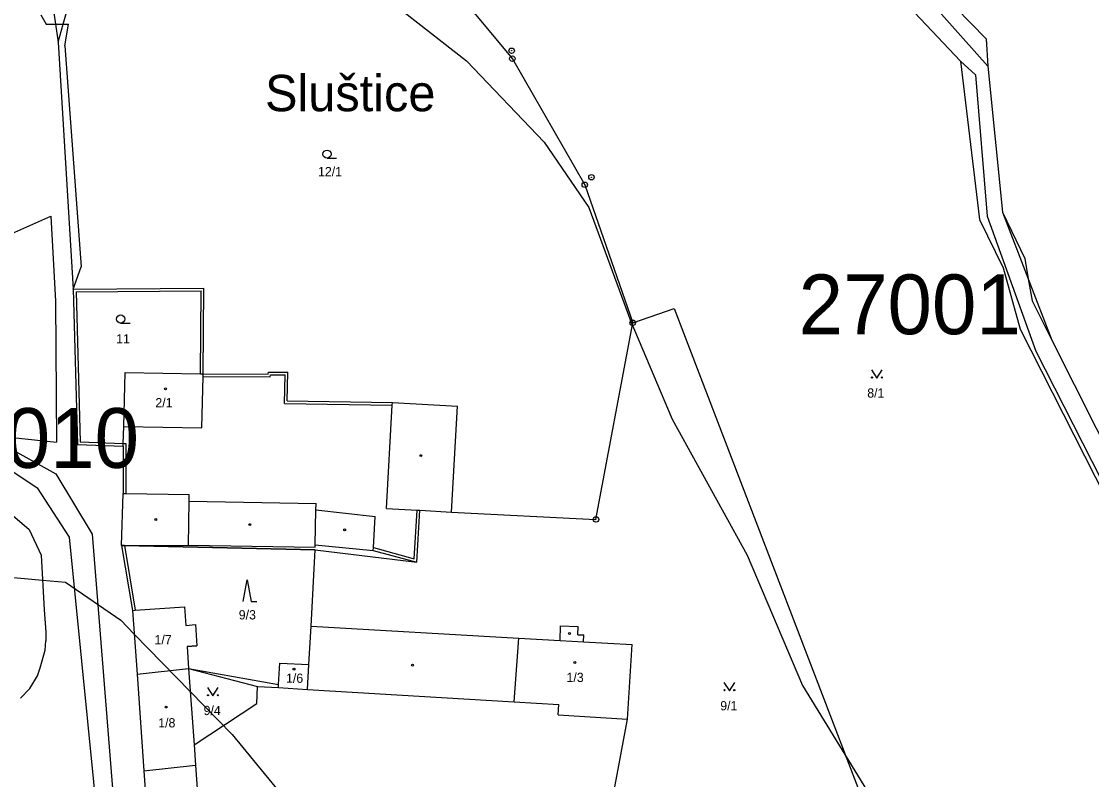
# Model space of a CAD drawing. Extents: x -725765 to -723182, y -1052705 to -1049154.
# Drawn here: x -724689.6 to -724492.6, y -1050911.3 to -1050771.8 of the extents above; entities that cross this region are included whole.
import ezdxf

# ---------------------------------------------------------------- set-up
doc = ezdxf.new("R2010")
doc.units = 0
for name, color, linetype in [('Vrstva 1', 7, 'Continuous'), ('Vrstva 15', 7, 'Continuous'), ('Vrstva 18', 7, 'Continuous'), ('Vrstva 19', 7, 'Continuous'), ('Vrstva 25', 7, 'Continuous'), ('Vrstva 4', 7, 'Continuous'), ('Vrstva 52', 7, 'Continuous'), ('Vrstva 53', 7, 'Continuous')]:
    doc.layers.add(name, color=color, linetype=linetype)

msp = doc.modelspace()

# ---------------------------------------------------------------- linework, layer by layer
at = {"layer": 'Vrstva 1'}
for points in [[(-724681.91, -1050772.28), (-724672.23, -1050738.03)], [(-724538.38, -1050749.99), (-724511.63, -1050779.98)], [(-724686.37, -1050751.98), (-724683.34, -1050772.29)], [(-724540.92, -1050753.35), (-724516.71, -1050779.1)], [(-724616.48, -1050757.85), (-724599.21, -1050778.62)], [(-724683.34, -1050772.29), (-724682.85, -1050775.6)], [(-724682.85, -1050775.6), (-724681.91, -1050772.28)], [(-724682.85, -1050775.6), (-724680.06, -1050821.02)], [(-724599.21, -1050778.62), (-724585.88, -1050801.83)], [(-724516.71, -1050779.1), (-724513.92, -1050781.58)], [(-724511.63, -1050779.98), (-724508.94, -1050806.85)], [(-724513.92, -1050781.58), (-724511.8, -1050807.6)], [(-724585.88, -1050801.83), (-724577.05, -1050827.24)], [(-724691.91, -1050811.03), (-724684.21, -1050807.61)], [(-724684.21, -1050807.61), (-724683.32, -1050823.25)], [(-724511.8, -1050807.6), (-724502.81, -1050832.47)], [(-724508.94, -1050806.85), (-724504.2, -1050819.15)], [(-724504.2, -1050819.15), (-724499.87, -1050830.41)], [(-724680.06, -1050821.02), (-724656.03, -1050820.88)], [(-724680.06, -1050821.02), (-724679.28, -1050849.63)], [(-724656.14, -1050836.64), (-724656.03, -1050820.88)], [(-724683.32, -1050823.25), (-724683.14, -1050849.22)], [(-724577.05, -1050827.24), (-724569.4, -1050824.59)], [(-724569.4, -1050824.59), (-724528.23, -1050932)], [(-724583.81, -1050863.44), (-724577.05, -1050827.24)], [(-724499.87, -1050830.41), (-724479.42, -1050870.99)], [(-724502.81, -1050832.47), (-724482.2, -1050872.94)], [(-724670.74, -1050846.33), (-724670.52, -1050836.4)], [(-724670.52, -1050836.4), (-724656.64, -1050836.63)], [(-724656.64, -1050836.63), (-724656.14, -1050836.64)], [(-724656.14, -1050836.64), (-724644.2, -1050836.67)], [(-724644.2, -1050836.67), (-724644.14, -1050836.32)], [(-724644.14, -1050836.32), (-724640.54, -1050836.33)], [(-724640.68, -1050841.61), (-724640.54, -1050836.33)], [(-724640.68, -1050841.61), (-724621.3, -1050841.91)], [(-724621.3, -1050841.91), (-724609.3, -1050842.57)], [(-724610.42, -1050862.09), (-724609.3, -1050842.57)], [(-724670.87, -1050849.43), (-724670.74, -1050846.33)], [(-724699.44, -1050847.52), (-724683.14, -1050849.22)], [(-724679.28, -1050849.63), (-724670.89, -1050849.93)], [(-724670.89, -1050849.93), (-724670.87, -1050849.43)], [(-724670.89, -1050849.93), (-724670.86, -1050858.65)], [(-724671.16, -1050868.22), (-724670.86, -1050858.65)], [(-724694.75, -1050859.69), (-724688.19, -1050865.28)], [(-724616.81, -1050871.32), (-724616.26, -1050861.75)], [(-724616.26, -1050861.75), (-724610.42, -1050862.09)], [(-724610.42, -1050862.09), (-724583.81, -1050863.44)], [(-724688.19, -1050865.28), (-724685.99, -1050869.99)], [(-724671.16, -1050868.22), (-724670.65, -1050868.23)], [(-724671.16, -1050868.22), (-724669.15, -1050880.2)], [(-724670.65, -1050868.23), (-724635.54, -1050869.06)], [(-724685.99, -1050869.99), (-724685.42, -1050880.08)], [(-724636.24, -1050883.08), (-724635.54, -1050869.06)], [(-724635.54, -1050869.06), (-724616.81, -1050871.32)], [(-724685.42, -1050880.08), (-724685.14, -1050884.21)], [(-724669.15, -1050880.2), (-724668.64, -1050880.16)], [(-724669.15, -1050880.2), (-724668.32, -1050891.93)], [(-724668.64, -1050880.16), (-724659.59, -1050879.54)], [(-724659.59, -1050879.54), (-724659.36, -1050882.97)], [(-724685.14, -1050884.21), (-724685.13, -1050885.78)], [(-724659.36, -1050882.97), (-724657.53, -1050882.8)], [(-724657.53, -1050882.8), (-724657.3, -1050886.68)], [(-724636.68, -1050890.14), (-724636.24, -1050883.08)], [(-724636.24, -1050883.08), (-724598, -1050885.27)], [(-724685.27, -1050887.49), (-724685.13, -1050885.78)], [(-724598.9, -1050896.99), (-724598, -1050885.27)], [(-724598, -1050885.27), (-724590.41, -1050885.7)], [(-724590.41, -1050885.7), (-724586.11, -1050885.95)], [(-724586.11, -1050885.95), (-724577.17, -1050886.46)], [(-724578.03, -1050900.23), (-724577.17, -1050886.46)], [(-724686.14, -1050890.78), (-724685.27, -1050887.49)], [(-724659.11, -1050886.82), (-724657.3, -1050886.68)], [(-724659.11, -1050886.82), (-724658.84, -1050890.87)], [(-724642.26, -1050893.8), (-724642.04, -1050889.9)], [(-724642.04, -1050889.9), (-724636.68, -1050890.14)], [(-724636.96, -1050894.71), (-724636.68, -1050890.14)], [(-724688.06, -1050894.53), (-724686.65, -1050892.25)], [(-724686.65, -1050892.25), (-724686.14, -1050890.78)], [(-724668.32, -1050891.93), (-724658.84, -1050890.87)], [(-724668.32, -1050891.93), (-724667.07, -1050909.73)], [(-724658.84, -1050890.87), (-724657.83, -1050904.95)], [(-724658.84, -1050890.87), (-724646.15, -1050894.16)], [(-724646.28, -1050897.31), (-724646.15, -1050894.16)], [(-724646.15, -1050894.16), (-724642.29, -1050894.39)], [(-724642.29, -1050894.39), (-724642.26, -1050893.8)], [(-724642.29, -1050894.39), (-724636.96, -1050894.71)], [(-724689.77, -1050896.34), (-724688.06, -1050894.53)], [(-724657.83, -1050904.95), (-724646.28, -1050897.31)], [(-724598.9, -1050896.99), (-724590.63, -1050897.48)], [(-724590.75, -1050899.43), (-724590.63, -1050897.48)], [(-724590.75, -1050899.43), (-724578.03, -1050900.23)], [(-724580.49, -1050913.34), (-724578.03, -1050900.23)], [(-724657.83, -1050904.95), (-724657.57, -1050908.64)], [(-724667.07, -1050909.73), (-724657.57, -1050908.64)], [(-724667.07, -1050909.73), (-724662.84, -1050969.87)]]:
    msp.add_lwpolyline(points, dxfattribs=at)
at = {"layer": 'Vrstva 25'}
for points in [[(-724633.34, -1050796.93), (-724631.59, -1050796.93)], [(-724671.35, -1050827.29), (-724669.6, -1050827.29)], [(-724533.09, -1050835.9), (-724532.09, -1050837.4), (-724531.09, -1050835.9)], [(-724648.79, -1050878.53), (-724648.04, -1050874.53), (-724647.29, -1050878.53), (-724646.29, -1050878.53)], [(-724655.36, -1050894.4), (-724654.36, -1050895.9), (-724653.36, -1050894.4)], [(-724560.24, -1050893.46), (-724559.24, -1050894.96), (-724558.24, -1050893.46)]]:
    msp.add_lwpolyline(points, dxfattribs=at)
for centre, radius in [((-724599.34, -1050777.15), 0.5), ((-724599.21, -1050778.62), 0.5), ((-724599.34, -1050777.15), 0.032), ((-724599.21, -1050778.62), 0.032), ((-724633.34, -1050796.18), 0.75), ((-724585.88, -1050801.83), 0.5), ((-724585.88, -1050801.83), 0.032), ((-724584.65, -1050800.44), 0.5), ((-724584.65, -1050800.44), 0.032), ((-724671.35, -1050826.54), 0.75), ((-724577.05, -1050827.24), 0.5), ((-724577.05, -1050827.24), 0.032), ((-724532.99, -1050837.3), 0.1), ((-724531.19, -1050837.3), 0.1), ((-724663.09, -1050839.41), 0.175), ((-724616.04, -1050851.69), 0.175), ((-724664.89, -1050863.43), 0.175), ((-724647.57, -1050864.39), 0.175), ((-724583.81, -1050863.44), 0.5), ((-724583.81, -1050863.44), 0.032), ((-724630.09, -1050865.35), 0.175), ((-724588.7, -1050884.44), 0.175), ((-724617.59, -1050890.27), 0.175), ((-724587.7, -1050889.78), 0.175), ((-724639.42, -1050890.99), 0.175), ((-724655.26, -1050895.8), 0.1), ((-724653.46, -1050895.8), 0.1), ((-724560.14, -1050894.86), 0.1), ((-724558.34, -1050894.86), 0.1), ((-724662.96, -1050897.97), 0.175)]:
    msp.add_circle(centre, radius, dxfattribs=at)
at = {"layer": 'Vrstva 4'}
for points in [[(-724537.52, -1050748.85), (-724511.99, -1050774.95)], [(-724686.05, -1050770.54), (-724685.05, -1050772.29)], [(-724685.05, -1050772.29), (-724683.34, -1050772.29)], [(-724683.34, -1050772.29), (-724681.91, -1050772.28)], [(-724681.91, -1050772.28), (-724680.94, -1050772.28)], [(-724681.59, -1050776.24), (-724680.94, -1050772.28)], [(-724511.99, -1050774.95), (-724511.63, -1050779.98)], [(-724681.59, -1050776.24), (-724678.6, -1050816.92)], [(-724516.71, -1050779.1), (-724513.17, -1050808.2)], [(-724508.94, -1050806.85), (-724504.85, -1050815.38)], [(-724513.17, -1050808.2), (-724508.86, -1050817.12)], [(-724504.85, -1050815.38), (-724504.2, -1050819.15)], [(-724680.06, -1050821.02), (-724678.6, -1050816.92)], [(-724508.86, -1050817.12), (-724505.7, -1050828.43)], [(-724504.2, -1050819.15), (-724503.51, -1050823.2)], [(-724679.55, -1050821.52), (-724656.53, -1050821.38)], [(-724679.55, -1050821.52), (-724678.79, -1050849.15)], [(-724656.64, -1050836.63), (-724656.53, -1050821.38)], [(-724503.51, -1050823.2), (-724499.87, -1050830.41)], [(-724505.7, -1050828.43), (-724482.04, -1050875.06)], [(-724656.37, -1050846.6), (-724656.15, -1050837.14)], [(-724656.15, -1050837.14), (-724656.14, -1050836.64)], [(-724656.15, -1050837.14), (-724643.78, -1050837.17)], [(-724643.78, -1050837.17), (-724643.72, -1050836.82)], [(-724643.72, -1050836.82), (-724641.05, -1050836.83)], [(-724641.19, -1050842.1), (-724641.05, -1050836.83)], [(-724641.19, -1050842.1), (-724621.33, -1050842.41)], [(-724622.41, -1050861.39), (-724621.33, -1050842.41)], [(-724621.33, -1050842.41), (-724621.3, -1050841.91)], [(-724670.74, -1050846.33), (-724656.37, -1050846.6)], [(-724691.02, -1050850.72), (-724683.3, -1050855.06)], [(-724678.79, -1050849.15), (-724670.87, -1050849.43)], [(-724670.87, -1050849.43), (-724670.39, -1050849.45)], [(-724670.39, -1050849.45), (-724670.36, -1050858.66)], [(-724691.95, -1050854.12), (-724686.7, -1050857.6)], [(-724683.3, -1050855.06), (-724676.58, -1050866.15)], [(-724686.7, -1050857.6), (-724680.8, -1050866.72)], [(-724670.86, -1050858.65), (-724670.36, -1050858.66)], [(-724670.36, -1050858.66), (-724658.71, -1050858.85)], [(-724658.73, -1050860.1), (-724658.71, -1050858.85)], [(-724658.86, -1050868.16), (-724658.73, -1050860.1)], [(-724658.73, -1050860.1), (-724635.36, -1050860.52)], [(-724635.38, -1050861.66), (-724635.36, -1050860.52)], [(-724635.5, -1050868.13), (-724635.38, -1050861.66)], [(-724635.38, -1050861.66), (-724624.46, -1050862.88)], [(-724624.79, -1050868.63), (-724624.46, -1050862.88)], [(-724622.41, -1050861.39), (-724616.76, -1050861.72)], [(-724617.27, -1050870.68), (-724616.76, -1050861.72)], [(-724616.76, -1050861.72), (-724616.26, -1050861.75)], [(-724680.8, -1050866.72), (-724674.09, -1050934.57)], [(-724676.58, -1050866.15), (-724671.12, -1050934.45)], [(-724671.16, -1050868.22), (-724658.86, -1050868.16)], [(-724670.65, -1050868.23), (-724668.64, -1050880.16)], [(-724658.86, -1050868.16), (-724635.51, -1050868.53)], [(-724635.51, -1050868.53), (-724635.5, -1050868.13)], [(-724635.5, -1050868.13), (-724624.82, -1050869.14)], [(-724624.82, -1050869.14), (-724624.79, -1050868.63)], [(-724624.79, -1050868.63), (-724617.27, -1050870.68)], [(-724624.82, -1050869.14), (-724616.81, -1050871.32)], [(-724590.41, -1050885.7), (-724590.33, -1050883)], [(-724590.33, -1050883), (-724587.12, -1050883.17)], [(-724587.14, -1050884.67), (-724587.12, -1050883.17)], [(-724587.14, -1050884.67), (-724586.06, -1050884.67)], [(-724586.11, -1050885.95), (-724586.06, -1050884.67)], [(-724658.84, -1050890.87), (-724642.26, -1050893.8)], [(-724636.96, -1050894.71), (-724598.9, -1050896.99)], [(-724657.57, -1050908.64), (-724654.32, -1050954.36)]]:
    msp.add_lwpolyline(points, dxfattribs=at)
at = {"layer": 'Vrstva 52'}
for points in [[(-724581.64, -1050708.13), (-724564.23, -1050728.57), (-724563.61, -1050729.23), (-724540.92, -1050753.35), (-724516.71, -1050779.1), (-724513.92, -1050781.58), (-724511.8, -1050807.6), (-724502.81, -1050832.47), (-724482.2, -1050872.94), (-724474.53, -1050880.96), (-724469.4, -1050885.71), (-724460.7, -1050890.93), (-724440.66, -1050902.59), (-724425.28, -1050906.29), (-724411.67, -1050908.97), (-724400.33, -1050906.21), (-724381.77, -1050899.99)], [(-724733.3, -1050722.26), (-724731.38, -1050724), (-724718.63, -1050730), (-724709.97, -1050732.26), (-724695.63, -1050736), (-724671.88, -1050741), (-724646.63, -1050753), (-724630.63, -1050761), (-724607.63, -1050779), (-724593.38, -1050794), (-724585.13, -1050806), (-724577.38, -1050827), (-724569.81, -1050845), (-724556, -1050870), (-724545.81, -1050894), (-724531.69, -1050917), (-724517.63, -1050935), (-724505.66, -1050947.46)], [(-724669.15, -1050880.2), (-724668.64, -1050880.16), (-724659.59, -1050879.54), (-724659.36, -1050882.97), (-724657.53, -1050882.8), (-724657.3, -1050886.68), (-724659.11, -1050886.82), (-724658.84, -1050890.87), (-724646.15, -1050894.16), (-724642.29, -1050894.39), (-724642.26, -1050893.8), (-724642.04, -1050889.9), (-724636.68, -1050890.14), (-724636.24, -1050883.08), (-724635.54, -1050869.06), (-724670.65, -1050868.23), (-724671.16, -1050868.22), (-724669.15, -1050880.2)], [(-724724.93, -1050961.09), (-724723.69, -1050959), (-724719.26, -1050944.99), (-724718.63, -1050943), (-724717.88, -1050938.42), (-724717.26, -1050934.62), (-724715.44, -1050923.42), (-724715.38, -1050923), (-724712.88, -1050902.63), (-724712.19, -1050897), (-724707.69, -1050884), (-724700.69, -1050877), (-724692.38, -1050874), (-724685.73, -1050874.61), (-724681.5, -1050875), (-724671.31, -1050882), (-724668.84, -1050884.53), (-724650.81, -1050903), (-724630.31, -1050928), (-724612.38, -1050961), (-724597.47, -1050993.67)]]:
    msp.add_lwpolyline(points, dxfattribs=at)

# ---------------------------------------------------------------- texts
at = {"layer": 'Vrstva 15'}
msp.add_text('Sluštice', height=6.7, dxfattribs=at).set_placement((-724644.75, -1050788.29))
at = {"layer": 'Vrstva 18'}
for s, p in [('12/1', (-724635, -1050800.25)), ('11', (-724672.17, -1050831.03)), ('8/1', (-724533.86, -1050841.01)), ('9/3', (-724649.59, -1050881.84)), ('9/4', (-724656.07, -1050899.45)), ('9/1', (-724560.93, -1050898.58))]:
    msp.add_text(s, height=1.7, dxfattribs=at).set_placement(p)
at = {"layer": 'Vrstva 19'}
for s, p in [('2/1', (-724664.95, -1050842.79)), ('1/7', (-724665.1, -1050886.41)), ('1/6', (-724640.89, -1050893.51)), ('1/3', (-724589.24, -1050893.36)), ('1/8', (-724664.42, -1050901.72))]:
    msp.add_text(s, height=1.7, dxfattribs=at).set_placement(p)
at = {"layer": 'Vrstva 53'}
for s, p in [('27001', (-724546.49, -1050829.34)), ('21010', (-724708.86, -1050853.94))]:
    msp.add_text(s, height=11, dxfattribs=at).set_placement(p)

doc.saveas('drawing.dxf')
